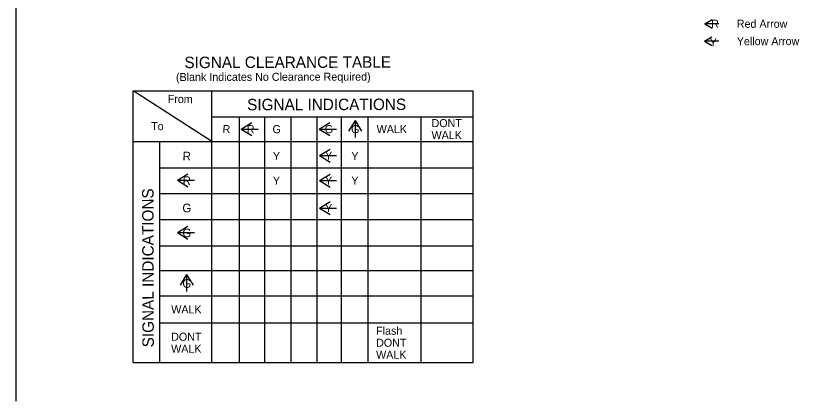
# Model space of a CAD drawing. Extents: x 10027 to 10796, y 10033 to 10528.
# Drawn here: x 10383.8 to 10726.2, y 10033.4 to 10201.9 of the extents above; entities that cross this region are included whole.
import ezdxf

# ---------------------------------------------------------------- set-up
doc = ezdxf.new("R2010")
doc.units = 0
for name, color, linetype in [('AdhocPoint_dp', 7, 'Continuous'), ('Default', 7, 'Continuous'), ('Dimension', 7, 'Continuous')]:
    doc.layers.add(name, color=color, linetype=linetype)

msp = doc.modelspace()

# ---------------------------------------------------------------- linework, layer by layer
at = {"layer": 'AdhocPoint_dp'}
for p, q in [((10383.78, 10205.22), (10383.78, 10033.43)), ((10435.19, 10169.11), (10583.66, 10169.11)), ((10435.19, 10050.37), (10435.19, 10169.11)), ((10469.49, 10146.96), (10435.19, 10169.11)), ((10469.49, 10050.37), (10469.49, 10169.11)), ((10583.66, 10050.37), (10583.66, 10169.11)), ((10469.49, 10157.79), (10583.66, 10157.79)), ((10481.66, 10050.37), (10481.66, 10157.79)), ((10492.66, 10050.37), (10492.66, 10157.79)), ((10504.1, 10050.37), (10504.1, 10157.79)), ((10515.47, 10050.37), (10515.47, 10157.79)), ((10526.17, 10050.37), (10526.17, 10157.63)), ((10537.81, 10050.37), (10537.81, 10157.79)), ((10560.92, 10050.37), (10560.92, 10157.79)), ((10435.19, 10146.96), (10583.66, 10146.96)), ((10446.71, 10050.37), (10446.71, 10146.96)), ((10446.71, 10135.45), (10583.66, 10135.45)), ((10446.71, 10124.27), (10583.66, 10124.27)), ((10446.71, 10112.87), (10583.66, 10112.87)), ((10446.71, 10101.42), (10583.66, 10101.42)), ((10446.71, 10090.57), (10583.66, 10090.57)), ((10446.71, 10079.54), (10583.66, 10079.54)), ((10446.71, 10067.67), (10583.66, 10067.67)), ((10435.19, 10050.37), (10583.66, 10050.37))]:
    msp.add_line(p, q, dxfattribs=at)
at = {"layer": 'Default'}
for p, q in [((10482.33, 10152.37), (10486.91, 10155.22)), ((10516.46, 10152.37), (10521.05, 10155.22)), ((10532.11, 10156.1), (10529.26, 10151.51)), ((10532.11, 10156.1), (10534.96, 10151.51)), ((10532.11, 10156.1), (10532.11, 10148.65)), ((10482.33, 10152.37), (10489.78, 10152.37)), ((10482.33, 10152.37), (10486.91, 10149.53)), ((10516.46, 10152.37), (10523.91, 10152.37)), ((10516.46, 10152.37), (10521.05, 10149.53)), ((10516.58, 10140.78), (10521.17, 10143.63)), ((10516.58, 10140.78), (10524.03, 10140.78)), ((10516.58, 10140.78), (10521.17, 10137.93)), ((10454.44, 10130.01), (10459.02, 10132.86)), ((10454.44, 10130.01), (10461.88, 10130.01)), ((10454.44, 10130.01), (10459.02, 10127.16)), ((10516.58, 10129.86), (10521.17, 10132.71)), ((10516.58, 10129.86), (10524.03, 10129.86)), ((10516.58, 10129.86), (10521.17, 10127.02)), ((10516.58, 10117.89), (10521.17, 10120.74)), ((10516.58, 10117.89), (10524.03, 10117.89)), ((10516.58, 10117.89), (10521.17, 10115.05)), ((10454.49, 10107.15), (10459.07, 10110)), ((10454.49, 10107.15), (10461.94, 10107.15)), ((10454.49, 10107.15), (10459.07, 10104.31)), ((10458.49, 10088.8), (10455.64, 10084.22)), ((10458.49, 10088.8), (10461.34, 10084.22)), ((10458.49, 10088.8), (10458.49, 10081.35))]:
    msp.add_line(p, q, dxfattribs=at)
at = {"layer": 'Dimension'}
for p, q in [((10684.87, 10198.4), (10688.08, 10200.31)), ((10684.87, 10198.4), (10688.11, 10196.47)), ((10691.04, 10198.4), (10684.87, 10198.4)), ((10684.82, 10190.8), (10688.03, 10192.71)), ((10684.82, 10190.8), (10688.05, 10188.88)), ((10690.99, 10190.8), (10684.82, 10190.8))]:
    msp.add_line(p, q, dxfattribs=at)

# ---------------------------------------------------------------- texts
at = {"layer": 'Default'}
for s, height, rotation, p in [('SIGNAL CLEARANCE TABLE', 5, 0.1183, (10457.52, 10179.02)), ('(Blank Indicates No Clearance Required)', 3.5, 0.1183, (10453.82, 10173.39)), ('From', 3.5, 359.1183, (10450.2, 10163.87)), ('SIGNAL INDICATIONS', 5, 0.1183, (10484.93, 10160.59)), ('To', 3.5, 359.1183, (10442.96, 10151.98)), ('SIGNAL INDICATIONS', 5, 90.1183, (10444.16, 10057.01))]:
    msp.add_text(s, height=height, rotation=rotation, dxfattribs=at).set_placement(p)
at = {"layer": 'Dimension'}
for s, p in [('R', (10687.69, 10196.68)), ('Red Arrow', (10698.91, 10196.65)), ('Y', (10687.06, 10188.51)), ('Yellow Arrow', (10698.91, 10189.05)), ('WALK', (10541.54, 10150.62)), ('DONT', (10565.51, 10153.25)), ('WALK', (10565.51, 10148)), ('WALK', (10451.77, 10071.85)), ('Flash', (10541.29, 10062.52)), ('DONT', (10451.72, 10059.89)), ('WALK', (10451.72, 10054.64)), ('DONT', (10541.29, 10057.27)), ('WALK', (10541.29, 10052.02))]:
    msp.add_text(s, height=3.5, dxfattribs=at).set_placement(p)
for s, height, p in [('R', 3.5, (10474.18, 10150.65)), ('R', 3.5, (10484.7, 10150.65)), ('G', 3.5, (10496, 10150.64)), ('G', 3.5, (10518.83, 10150.64)), ('G', 3.5, (10530.32, 10150.64)), ('R', 3.78, (10456.68, 10138.72)), ('Y', 3.5, (10496.12, 10138.86)), ('Y', 3.5, (10518.95, 10139.05)), ('Y', 3.5, (10530.43, 10138.86)), ('R', 3.78, (10456.68, 10128)), ('Y', 3.5, (10496.12, 10128.13)), ('Y', 3.5, (10518.95, 10128.13)), ('Y', 3.5, (10530.43, 10128.13)), ('G', 3.78, (10456.6, 10116.03)), ('Y', 3.5, (10518.95, 10116.16)), ('G', 3.78, (10456.6, 10105.14)), ('G', 3.78, (10456.6, 10083.07))]:
    msp.add_text(s, height=height, rotation=359.1183, dxfattribs=at).set_placement(p)

doc.saveas('drawing.dxf')
